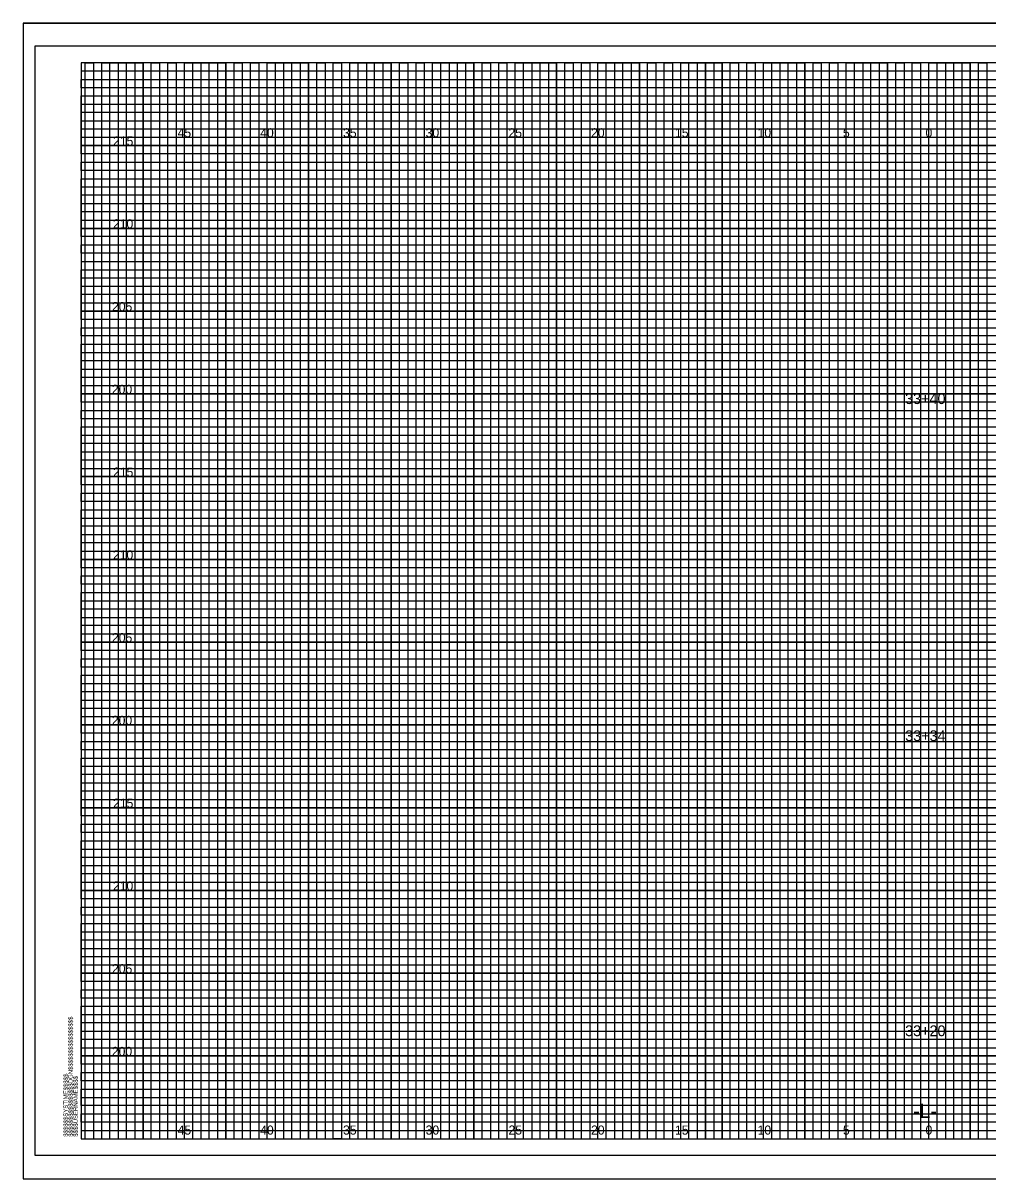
# Model space of a CAD drawing. Extents: x -4 to 103, y -2 to 6583.
# Drawn here: x -3.5 to 54.8, y 2264 to 2333.8 of the extents above; entities that cross this region are included whole.
import ezdxf

# ---------------------------------------------------------------- set-up
doc = ezdxf.new("R2010")
doc.units = 0
for name, color, linetype in [('Prop XS Alignment Label', 7, 'Continuous'), ('Prop XS Elevation Labels', 7, 'Continuous'), ('Prop XS Offset Labels', 7, 'Continuous'), ('Prop XS Station Labels', 7, 'Continuous'), ('Sheet Cross Section CELL', 7, 'Continuous'), ('Sheet Cross Section Grid Major CELL', 7, 'Continuous'), ('Sheet Cross Section Grid Middle CELL', 7, 'Continuous'), ('Sheet Cutting Line CELL', 7, 'Continuous'), ('Sheet DOT Grid CELL', 7, 'Continuous'), ('Sheet Plot Border Inside CELL', 7, 'Continuous'), ('Sheet Plot Border Outside CELL', 7, 'Continuous')]:
    doc.layers.add(name, color=color, linetype=linetype)

msp = doc.modelspace()

# ---------------------------------------------------------------- linework, layer by layer
at = {"layer": 'Sheet Cross Section CELL'}
msp.add_lwpolyline([(102.5, 2331.4), (0, 2331.4), (0, 2266.4), (102.5, 2266.4)], close=True, dxfattribs=at)
at = {"layer": 'Sheet Cross Section Grid Major CELL'}
for points in [[(1.25, 2266.4), (1.25, 2331.4), (3.75, 2331.4), (3.75, 2266.4), (6.25, 2266.4), (6.25, 2331.4), (8.75, 2331.4), (8.75, 2266.4), (11.25, 2266.4), (11.25, 2331.4), (13.75, 2331.4), (13.75, 2266.4), (16.25, 2266.4), (16.25, 2331.4), (18.75, 2331.4), (18.75, 2266.4), (21.25, 2266.4), (21.25, 2331.4), (23.75, 2331.4), (23.75, 2266.4), (26.25, 2266.4), (26.25, 2331.4), (28.75, 2331.4), (28.75, 2266.4), (31.25, 2266.4), (31.25, 2331.4), (33.75, 2331.4), (33.75, 2266.4), (36.25, 2266.4), (36.25, 2331.4), (38.75, 2331.4), (38.75, 2266.4), (41.25, 2266.4), (41.25, 2331.4), (43.75, 2331.4), (43.75, 2266.4), (46.25, 2266.4), (46.25, 2331.4), (48.75, 2331.4), (48.75, 2266.4), (51.25, 2266.4), (51.25, 2331.4), (53.75, 2331.4), (53.75, 2266.4)], [(102.5, 2326.4), (0, 2326.4), (0, 2328.9), (74.25, 2328.9)], [(102.5, 2321.4), (0, 2321.4), (0, 2323.9), (102.5, 2323.9)], [(102.5, 2316.4), (0, 2316.4), (0, 2318.9), (102.5, 2318.9)], [(102.5, 2311.4), (0, 2311.4), (0, 2313.9), (102.5, 2313.9)], [(102.5, 2306.4), (0, 2306.4), (0, 2308.9), (102.5, 2308.9)], [(102.5, 2301.4), (0, 2301.4), (0, 2303.9), (102.5, 2303.9)], [(102.5, 2296.4), (0, 2296.4), (0, 2298.9), (102.5, 2298.9)], [(102.5, 2291.4), (0, 2291.4), (0, 2293.9), (102.5, 2293.9)], [(102.5, 2286.4), (0, 2286.4), (0, 2288.9), (102.5, 2288.9)], [(102.5, 2281.4), (0, 2281.4), (0, 2283.9), (102.5, 2283.9)], [(102.5, 2276.4), (0, 2276.4), (0, 2278.9), (102.5, 2278.9)], [(102.5, 2271.4), (0, 2271.4), (0, 2273.9), (102.5, 2273.9)], [(0, 2268.9), (102.5, 2268.9)]]:
    msp.add_lwpolyline(points, dxfattribs=at)
at = {"layer": 'Sheet Cross Section Grid Middle CELL'}
for points in [[(0, 2328.4), (0, 2329.4), (74.25, 2329.4), (74.25, 2329.9), (0, 2329.9), (0, 2330.4), (74.25, 2330.4), (74.25, 2330.9), (0, 2330.9)], [(0.25, 2266.4), (0.25, 2331.4), (0.75, 2331.4), (0.75, 2266.4), (1.75, 2266.4), (1.75, 2331.4), (2.25, 2331.4), (2.25, 2266.4), (2.75, 2266.4), (2.75, 2331.4), (3.25, 2331.4), (3.25, 2266.4), (4.25, 2266.4), (4.25, 2331.4), (4.75, 2331.4), (4.75, 2266.4), (5.25, 2266.4), (5.25, 2331.4), (5.75, 2331.4), (5.75, 2266.4), (6.75, 2266.4), (6.75, 2331.4), (7.25, 2331.4), (7.25, 2266.4), (7.75, 2266.4), (7.75, 2331.4), (8.25, 2331.4), (8.25, 2266.4), (9.25, 2266.4), (9.25, 2331.4), (9.75, 2331.4), (9.75, 2266.4), (10.25, 2266.4), (10.25, 2331.4), (10.75, 2331.4), (10.75, 2266.4), (11.75, 2266.4), (11.75, 2331.4), (12.25, 2331.4), (12.25, 2266.4), (12.75, 2266.4), (12.75, 2331.4), (13.25, 2331.4), (13.25, 2266.4), (14.25, 2266.4), (14.25, 2331.4), (14.75, 2331.4), (14.75, 2266.4), (15.75, 2266.4), (15.25, 2266.4), (15.25, 2331.4), (15.75, 2331.4), (15.75, 2266.4), (16.75, 2266.4), (16.75, 2331.4), (17.25, 2331.4), (17.25, 2266.4), (17.75, 2266.4), (17.75, 2331.4), (18.25, 2331.4), (18.25, 2266.4), (19.25, 2266.4), (19.25, 2331.4), (19.75, 2331.4), (19.75, 2266.4), (20.25, 2266.4), (20.25, 2331.4), (20.75, 2331.4), (20.75, 2266.4), (21.75, 2266.4), (21.75, 2331.4), (22.25, 2331.4), (22.25, 2266.4), (22.75, 2266.4), (22.75, 2331.4), (23.25, 2331.4), (23.25, 2266.4), (24.25, 2266.4), (24.25, 2331.4), (24.75, 2331.4), (24.75, 2266.4), (25.25, 2266.4), (25.25, 2331.4), (25.75, 2331.4), (25.75, 2266.4), (26.75, 2266.4), (26.75, 2331.4), (27.25, 2331.4), (27.25, 2266.4), (27.75, 2266.4), (27.75, 2331.4), (28.25, 2331.4), (28.25, 2266.4), (29.25, 2266.4), (29.25, 2331.4), (29.75, 2331.4), (29.75, 2266.4), (30.25, 2266.4), (30.25, 2331.4), (30.75, 2331.4), (30.75, 2266.4)], [(30.75, 2266.4), (31.75, 2266.4), (31.75, 2331.4), (32.25, 2331.4), (32.25, 2266.4), (32.75, 2266.4), (32.75, 2331.4), (33.25, 2331.4), (33.25, 2266.4), (34.25, 2266.4), (34.25, 2331.4), (34.75, 2331.4), (34.75, 2266.4), (35.25, 2266.4), (35.25, 2331.4), (35.75, 2331.4), (35.75, 2266.4), (36.75, 2266.4), (36.75, 2331.4), (37.25, 2331.4), (37.25, 2266.4), (37.75, 2266.4), (37.75, 2331.4), (37.75, 2266.4)], [(38.25, 2331.4), (38.25, 2266.4), (39.25, 2266.4), (39.25, 2331.4), (39.75, 2331.4), (39.75, 2266.4), (40.25, 2266.4), (40.25, 2331.4), (40.75, 2331.4), (40.75, 2266.4), (41.75, 2266.4), (41.75, 2331.4), (42.25, 2331.4), (42.25, 2266.4), (42.75, 2266.4), (42.75, 2331.4), (43.25, 2331.4), (43.25, 2266.4), (43.75, 2266.4), (44.25, 2266.4), (44.25, 2331.4), (44.75, 2331.4), (44.75, 2266.4), (45.25, 2266.4), (45.25, 2331.4), (45.75, 2331.4), (45.75, 2266.4), (46.75, 2266.4), (46.75, 2331.4), (47.25, 2331.4), (47.25, 2266.4), (47.75, 2266.4), (47.75, 2331.4), (48.25, 2331.4), (48.25, 2266.4), (49.25, 2266.4), (49.25, 2331.4), (49.75, 2331.4), (49.75, 2266.4), (50.25, 2266.4), (50.25, 2331.4), (50.75, 2331.4), (50.75, 2266.4), (51.75, 2266.4), (51.75, 2331.4), (52.25, 2331.4), (52.25, 2266.4), (52.75, 2266.4), (52.75, 2331.4), (53.25, 2331.4), (53.25, 2266.4), (54.25, 2266.4), (54.25, 2331.4), (54.75, 2331.4), (54.75, 2266.4), (55.25, 2266.4)], [(102.5, 2328.4), (0, 2328.4)], [(102.5, 2327.4), (0, 2327.4), (0, 2327.9), (102.5, 2327.9)], [(102.5, 2325.9), (0, 2325.9), (0, 2326.9), (102.5, 2326.9)], [(102.5, 2324.9), (0, 2324.9), (0, 2325.4), (102.5, 2325.4)], [(102.5, 2323.4), (0, 2323.4), (0, 2324.4), (102.5, 2324.4)], [(102.5, 2322.4), (0, 2322.4), (0, 2322.9), (102.5, 2322.9)], [(102.5, 2320.9), (0, 2320.9), (0, 2321.9), (102.5, 2321.9)], [(102.5, 2319.9), (0, 2319.9), (0, 2320.4), (102.5, 2320.4)], [(0, 2319.4), (102.5, 2319.4)], [(102.5, 2318.4), (0, 2318.4)], [(102.5, 2317.4), (0, 2317.4), (0, 2317.9), (102.5, 2317.9)], [(102.5, 2315.9), (0, 2315.9), (0, 2316.9), (102.5, 2316.9)], [(102.5, 2314.9), (0, 2314.9), (0, 2315.4), (102.5, 2315.4)], [(102.5, 2313.4), (0, 2313.4), (0, 2314.4), (102.5, 2314.4)], [(102.5, 2312.4), (0, 2312.4), (0, 2312.9), (102.5, 2312.9)], [(102.5, 2310.9), (0, 2310.9), (0, 2311.9), (102.5, 2311.9)], [(102.5, 2309.9), (0, 2309.9), (0, 2310.4), (102.5, 2310.4)], [(102.5, 2308.4), (0, 2308.4), (0, 2309.4), (102.5, 2309.4)], [(102.5, 2307.4), (0, 2307.4), (0, 2307.9), (102.5, 2307.9)], [(102.5, 2305.9), (0, 2305.9), (0, 2306.9), (102.5, 2306.9)], [(102.5, 2304.9), (0, 2304.9), (0, 2305.4), (102.5, 2305.4)], [(102.5, 2303.4), (0, 2303.4), (0, 2304.4), (102.5, 2304.4)], [(102.5, 2302.4), (0, 2302.4), (0, 2302.9), (102.5, 2302.9)], [(102.5, 2300.9), (0, 2300.9), (0, 2301.9), (102.5, 2301.9)], [(102.5, 2299.9), (0, 2299.9), (0, 2300.4), (102.5, 2300.4)], [(102.5, 2298.4), (0, 2298.4), (0, 2299.4), (102.5, 2299.4)], [(102.5, 2297.4), (0, 2297.4), (0, 2297.9)], [(0, 2297.9), (102.5, 2297.9)], [(102.5, 2295.9), (0, 2295.9), (0, 2296.9), (102.5, 2296.9)], [(102.5, 2294.9), (0, 2294.9), (0, 2295.4), (102.5, 2295.4)], [(102.5, 2293.4), (0, 2293.4), (0, 2294.4), (102.5, 2294.4)], [(102.5, 2292.4), (0, 2292.4), (0, 2292.9), (102.5, 2292.9)], [(102.5, 2290.9), (0, 2290.9), (0, 2291.9), (102.5, 2291.9)], [(102.5, 2289.9), (0, 2289.9), (0, 2290.4), (102.5, 2290.4)], [(102.5, 2288.4), (0, 2288.4), (0, 2289.4), (102.5, 2289.4)], [(102.5, 2287.4), (0, 2287.4), (0, 2287.9), (102.5, 2287.9)], [(102.5, 2285.9), (0, 2285.9), (0, 2286.9), (102.5, 2286.9)], [(102.5, 2284.9), (0, 2284.9), (0, 2285.4), (102.5, 2285.4)], [(102.5, 2283.4), (0, 2283.4), (0, 2284.4), (102.5, 2284.4)], [(102.5, 2282.4), (0, 2282.4), (0, 2282.9), (102.5, 2282.9)], [(102.5, 2280.9), (0, 2280.9), (0, 2281.9), (102.5, 2281.9)], [(102.5, 2279.9), (0, 2279.9), (0, 2280.4), (102.5, 2280.4)], [(102.5, 2278.4), (0, 2278.4), (0, 2279.4), (102.5, 2279.4)], [(102.5, 2277.4), (0, 2277.4), (0, 2277.9), (102.5, 2277.9)], [(102.5, 2275.9), (0, 2275.9), (0, 2276.9), (102.5, 2276.9)], [(102.5, 2274.9), (0, 2274.9), (0, 2275.4), (102.5, 2275.4)], [(102.5, 2273.4), (0, 2273.4), (0, 2274.4), (102.5, 2274.4)], [(102.5, 2272.4), (0, 2272.4), (0, 2272.9), (102.5, 2272.9)], [(102.5, 2270.9), (0, 2270.9), (0, 2271.9), (102.5, 2271.9)], [(102.5, 2269.9), (0, 2269.9), (0, 2270.4), (102.5, 2270.4)], [(102.5, 2268.4), (0, 2268.4), (0, 2269.4), (102.5, 2269.4)], [(102.5, 2267.4), (0, 2267.4), (0, 2267.9), (102.5, 2267.9)], [(0, 2266.9), (102.5, 2266.9)]]:
    msp.add_lwpolyline(points, dxfattribs=at)
at = {"layer": 'Sheet Cutting Line CELL'}
for p, q in [((-3.5, 2333.8), (103.4, 2333.8)), ((-3.5, 2333.8), (-3.5, 2263.975)), ((-3.5, 2263.975), (103.4, 2263.975))]:
    msp.add_line(p, q, dxfattribs=at)
at = {"layer": 'Sheet DOT Grid CELL'}
for p, q in [((1.25, 2266.4), (1.25, 2331.4)), ((3.75, 2266.4), (3.75, 2331.4)), ((6.25, 2266.4), (6.25, 2331.4)), ((8.75, 2266.4), (8.75, 2331.4)), ((11.25, 2266.4), (11.25, 2331.4)), ((13.75, 2266.4), (13.75, 2331.4)), ((16.25, 2266.4), (16.25, 2331.4)), ((18.75, 2266.4), (18.75, 2331.4)), ((21.25, 2266.4), (21.25, 2331.4)), ((23.75, 2266.4), (23.75, 2331.4)), ((26.25, 2266.4), (26.25, 2331.4)), ((28.75, 2266.4), (28.75, 2331.4)), ((31.25, 2266.4), (31.25, 2331.4)), ((33.75, 2266.4), (33.75, 2331.4)), ((36.25, 2266.4), (36.25, 2331.4)), ((38.75, 2266.4), (38.75, 2331.4)), ((41.25, 2266.4), (41.25, 2331.4)), ((43.75, 2266.4), (43.75, 2331.4)), ((46.25, 2266.4), (46.25, 2331.4)), ((48.75, 2266.4), (48.75, 2331.4)), ((51.25, 2266.4), (51.25, 2331.4)), ((53.75, 2266.4), (53.75, 2331.4)), ((0, 2328.9), (74.25, 2328.9)), ((0, 2326.4), (102.5, 2326.4)), ((0, 2323.9), (102.5, 2323.9)), ((0, 2321.4), (102.5, 2321.4)), ((0, 2318.9), (102.5, 2318.9)), ((0, 2316.4), (102.5, 2316.4)), ((0, 2313.9), (102.5, 2313.9)), ((0, 2311.4), (102.5, 2311.4)), ((0, 2308.9), (102.5, 2308.9)), ((0, 2306.4), (102.5, 2306.4)), ((0, 2303.9), (102.5, 2303.9)), ((0, 2301.4), (102.5, 2301.4)), ((0, 2298.9), (102.5, 2298.9)), ((0, 2296.4), (102.5, 2296.4)), ((0, 2293.9), (102.5, 2293.9)), ((0, 2291.4), (102.5, 2291.4)), ((0, 2288.9), (102.5, 2288.9)), ((0, 2286.4), (102.5, 2286.4)), ((0, 2283.9), (102.5, 2283.9)), ((0, 2281.4), (102.5, 2281.4)), ((0, 2278.9), (102.5, 2278.9)), ((0, 2276.4), (102.5, 2276.4)), ((0, 2273.9), (102.5, 2273.9)), ((0, 2271.4), (102.5, 2271.4)), ((0, 2268.9), (102.5, 2268.9))]:
    msp.add_line(p, q, dxfattribs=at)
at = {"layer": 'Sheet Plot Border Inside CELL'}
msp.add_lwpolyline([(103, 2332.4), (-2.8, 2332.4), (-2.8, 2265.4), (103, 2265.4)], close=True, dxfattribs=at)
at = {"layer": 'Sheet Plot Border Outside CELL'}
msp.add_lwpolyline([(103.4, 2333.8), (-3.5, 2333.8), (-3.5, 2263.975), (103.4, 2263.975)], close=True, dxfattribs=at)

# ---------------------------------------------------------------- texts
at = {"layer": 'Prop XS Alignment Label'}
msp.add_text('-L-', height=0.875, dxfattribs=at).set_placement((50.307, 2267.65))
at = {"layer": 'Prop XS Elevation Labels'}
for s, p in [('215', (1.938, 2326.4)), ('210', (1.93, 2321.4)), ('205', (1.872, 2316.4)), ('200', (1.864, 2311.4)), ('215', (1.938, 2306.4)), ('210', (1.93, 2301.4)), ('205', (1.872, 2296.4)), ('200', (1.864, 2291.4)), ('215', (1.938, 2286.4)), ('210', (1.93, 2281.4)), ('205', (1.872, 2276.4)), ('200', (1.864, 2271.4))]:
    msp.add_text(s, height=0.55, dxfattribs=at).set_placement(p)
at = {"layer": 'Prop XS Offset Labels'}
for s, p in [('45', (5.84, 2326.9)), ('40', (10.831, 2326.9)), ('35', (15.84, 2326.9)), ('30', (20.831, 2326.9)), ('25', (25.84, 2326.9)), ('20', (30.831, 2326.9)), ('15', (35.906, 2326.9)), ('10', (40.897, 2326.9)), ('5', (46.057, 2326.9)), ('0', (51.049, 2326.9)), ('0', (51.049, 2326.9)), ('45', (5.84, 2266.65)), ('40', (10.831, 2266.65)), ('35', (15.84, 2266.65)), ('30', (20.831, 2266.65)), ('25', (25.84, 2266.65)), ('20', (30.831, 2266.65)), ('15', (35.906, 2266.65)), ('10', (40.897, 2266.65)), ('5', (46.057, 2266.65)), ('0', (51.049, 2266.65)), ('0', (51.049, 2266.65))]:
    msp.add_text(s, height=0.55, dxfattribs=at).set_placement(p)
at = {"layer": 'Prop XS Station Labels'}
for s, p in [('33+40', (49.816, 2310.787)), ('33+34', (49.82, 2290.424)), ('33+20', (49.816, 2272.597))]:
    msp.add_text(s, height=0.65, dxfattribs=at).set_placement(p)
at = {"layer": 'Sheet Cross Section CELL'}
for s, p in [('$$$$$$$$$$$$$$$$DGN$$$$$$$$$$$$$$$$', (-0.5, 2266.525)), ('$$$$$$SYSTIME$$$$$', (-0.797, 2266.525)), ('$$$$USERNAME$$$$', (-0.2, 2266.525))]:
    msp.add_text(s, height=0.2625, rotation=90, dxfattribs=at).set_placement(p)
at = {"layer": 'Sheet Cross Section Grid Major CELL'}
msp.add_text('040397', height=0.0025, rotation=90, dxfattribs=at).set_placement((-0.001, 2331.386))

doc.saveas('drawing.dxf')
